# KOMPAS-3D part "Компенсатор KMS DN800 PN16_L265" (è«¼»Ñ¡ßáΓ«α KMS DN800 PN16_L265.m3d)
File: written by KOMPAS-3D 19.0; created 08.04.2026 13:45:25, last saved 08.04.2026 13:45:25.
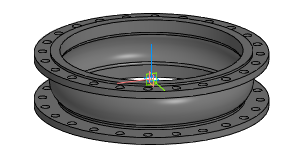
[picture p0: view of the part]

Document properties: Автор: Энергия; Полное имя файла: Z:\3.Личные\kachalov\3d для проектировщиков\7.1 Компенсатор\stp_Компенсатор KSM\Компенсатор KMS DN800 PN16_L265.m3d

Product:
- Part/product: Компенсатор KMS DN800 PN16_L265

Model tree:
1. Операция без истории:1  (labels: Компенсатор KMS DN800 PN16_L265)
